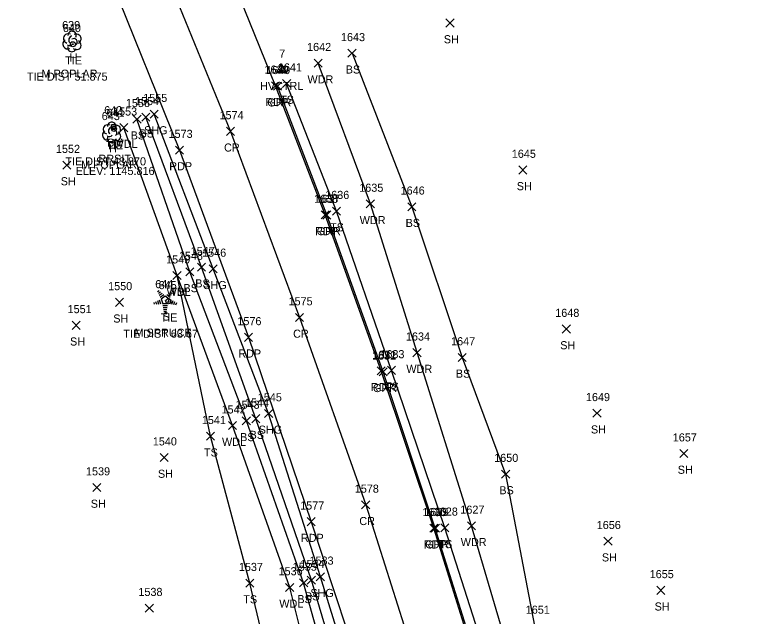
# Model space of a CAD drawing. Extents: x 1545627 to 1546562, y 571176 to 576667.
# Drawn here: x 1545906.1 to 1546091.5, y 572663.2 to 572811.9 of the extents above; entities that cross this region are included whole.
import ezdxf

# ---------------------------------------------------------------- set-up
doc = ezdxf.new("R2010")
doc.units = 0
for name, color, linetype in [('C_A', 7, 'Continuous'), ('C_C', 7, 'Continuous'), ('C_I', 7, 'Continuous'), ('CBP', 7, 'Continuous'), ('CPBM', 7, 'Continuous'), ('CPSM', 7, 'Continuous'), ('L_A', 7, 'Continuous'), ('L_C', 7, 'Continuous'), ('L_I', 7, 'Continuous'), ('L_TIC', 7, 'Continuous'), ('LAWA', 7, 'Continuous'), ('LELB', 7, 'Continuous'), ('LTC', 7, 'Continuous'), ('LTD', 7, 'Continuous'), ('P_A', 7, 'Continuous'), ('P_I', 7, 'Continuous'), ('P_TIC', 7, 'Continuous'), ('PET', 7, 'Continuous'), ('PRC', 7, 'Continuous'), ('PSU', 7, 'Continuous'), ('R_A', 7, 'Continuous'), ('R_I', 7, 'Continuous'), ('R_TIC', 7, 'Continuous'), ('RGR', 7, 'Continuous')]:
    doc.layers.add(name, color=color, linetype=linetype)

msp = doc.modelspace()

# ---------------------------------------------------------------- linework, layer by layer
at = {"layer": 'CBP'}
for centre, radius in [((1545920.38, 572804.67), 0.625), ((1545920.38, 572804.67), 0.0833), ((1545930.51, 572783.73), 0.625), ((1545930.51, 572783.73), 0.0833), ((1545943.94, 572741.15), 0.625), ((1545943.94, 572741.15), 0.0833)]:
    msp.add_circle(centre, radius, dxfattribs=at)
at = {"layer": 'CPBM'}
for p, q in [((1545929.99, 572783.86), (1545929.99, 572784.86)), ((1545929.99, 572784.86), (1545930.99, 572784.86)), ((1545930.5, 572784.36), (1545930.5, 572784.36)), ((1545930.5, 572784.36), (1545930.5, 572784.36)), ((1545930.99, 572784.86), (1545930.99, 572783.86)), ((1545930.99, 572783.86), (1545929.99, 572783.86))]:
    msp.add_line(p, q, dxfattribs=at)
at = {"layer": 'CPSM'}
for p, q in [((1545970.62, 572797.64), (1545971.87, 572799.81)), ((1545973.12, 572797.64), (1545971.87, 572799.81)), ((1545971.87, 572798.36), (1545971.87, 572799.81)), ((1545970.62, 572797.64), (1545971.87, 572798.36)), ((1545970.62, 572797.64), (1545973.12, 572797.64)), ((1545971.87, 572798.36), (1545971.87, 572798.36)), ((1545971.87, 572798.36), (1545973.12, 572797.64))]:
    msp.add_line(p, q, dxfattribs=at)
at = {"layer": 'L_TIC'}
for points in [[(1546012.47, 572808.9), (1546014.47, 572810.9)], [(1546014.47, 572808.9), (1546012.47, 572810.9)], [(1545988.29, 572801.43), (1545990.29, 572803.43)], [(1545990.29, 572801.43), (1545988.29, 572803.43)], [(1545979.93, 572798.99), (1545981.93, 572800.99)], [(1545981.93, 572798.99), (1545979.93, 572800.99)], [(1545972.14, 572793.95), (1545974.14, 572795.95)], [(1545974.14, 572793.95), (1545972.14, 572795.95)], [(1545935.18, 572785.14), (1545937.18, 572787.14)], [(1545937.18, 572785.14), (1545935.18, 572787.14)], [(1545937.38, 572785.62), (1545939.38, 572787.62)], [(1545939.38, 572785.62), (1545937.38, 572787.62)], [(1545931.96, 572783.05), (1545933.96, 572785.05)], [(1545933.96, 572783.05), (1545931.96, 572785.05)], [(1545917.86, 572773.81), (1545919.86, 572775.81)], [(1545919.86, 572773.81), (1545917.86, 572775.81)], [(1546030.48, 572772.6), (1546032.48, 572774.6)], [(1546032.48, 572772.6), (1546030.48, 572774.6)], [(1545992.81, 572764.21), (1545994.81, 572766.21)], [(1545994.81, 572764.21), (1545992.81, 572766.21)], [(1546003.07, 572763.52), (1546005.07, 572765.52)], [(1546005.07, 572763.52), (1546003.07, 572765.52)], [(1545984.45, 572762.44), (1545986.45, 572764.44)], [(1545986.45, 572762.44), (1545984.45, 572764.44)], [(1545948.22, 572747.41), (1545950.22, 572749.41)], [(1545950.22, 572747.41), (1545948.22, 572749.41)], [(1545951.14, 572748.58), (1545953.14, 572750.58)], [(1545953.14, 572748.58), (1545951.14, 572750.58)], [(1545945.07, 572746.5), (1545947.07, 572748.5)], [(1545947.07, 572746.5), (1545945.07, 572748.5)], [(1545945.07, 572746.5), (1545947.07, 572748.5)], [(1545947.07, 572746.5), (1545945.07, 572748.5)], [(1545930.84, 572739.9), (1545932.84, 572741.9)], [(1545932.84, 572739.9), (1545930.84, 572741.9)], [(1545920.18, 572734.22), (1545922.18, 572736.22)], [(1545922.18, 572734.22), (1545920.18, 572736.22)], [(1546041.21, 572733.3), (1546043.21, 572735.3)], [(1546043.21, 572733.3), (1546041.21, 572735.3)], [(1546004.34, 572727.46), (1546006.34, 572729.46)], [(1546006.34, 572727.46), (1546004.34, 572729.46)], [(1546015.49, 572726.28), (1546017.49, 572728.28)], [(1546017.49, 572726.28), (1546015.49, 572728.28)], [(1545998.02, 572723.09), (1546000.02, 572725.09)], [(1546000.02, 572723.09), (1545998.02, 572725.09)], [(1546048.79, 572712.49), (1546050.79, 572714.49)], [(1546050.79, 572712.49), (1546048.79, 572714.49)], [(1545962.2, 572710.6), (1545964.2, 572712.6)], [(1545964.2, 572710.6), (1545962.2, 572712.6)], [(1545964.55, 572711.15), (1545966.55, 572713.15)], [(1545966.55, 572711.15), (1545964.55, 572713.15)], [(1545958.77, 572709.44), (1545960.77, 572711.44)], [(1545960.77, 572709.44), (1545958.77, 572711.44)], [(1545953.32, 572706.82), (1545955.32, 572708.82)], [(1545955.32, 572706.82), (1545953.32, 572708.82)], [(1546070.23, 572702.53), (1546072.23, 572704.53)], [(1546072.23, 572702.53), (1546070.23, 572704.53)], [(1545941.87, 572701.54), (1545943.87, 572703.54)], [(1545943.87, 572701.54), (1545941.87, 572703.54)], [(1546026.22, 572697.47), (1546028.22, 572699.47)], [(1546028.22, 572697.47), (1546026.22, 572699.47)], [(1545925.29, 572694.14), (1545927.29, 572696.14)], [(1545927.29, 572694.14), (1545925.29, 572696.14)], [(1546011.21, 572684.19), (1546013.21, 572686.19)], [(1546013.21, 572684.19), (1546011.21, 572686.19)], [(1546017.77, 572684.67), (1546019.77, 572686.67)], [(1546019.77, 572684.67), (1546017.77, 572686.67)], [(1546051.5, 572680.88), (1546053.5, 572682.88)], [(1546053.5, 572680.88), (1546051.5, 572682.88)], [(1545978.25, 572671.26), (1545980.25, 572673.26)], [(1545980.25, 572671.26), (1545978.25, 572673.26)], [(1545963.04, 572670.52), (1545965.04, 572672.52)], [(1545965.04, 572670.52), (1545963.04, 572672.52)], [(1545972.9, 572669.46), (1545974.9, 572671.46)], [(1545974.9, 572669.46), (1545972.9, 572671.46)], [(1545976.34, 572670.58), (1545978.34, 572672.58)], [(1545978.34, 572670.58), (1545976.34, 572672.58)], [(1546064.53, 572668.75), (1546066.53, 572670.75)], [(1546066.53, 572668.75), (1546064.53, 572670.75)], [(1545938.23, 572664.35), (1545940.23, 572666.35)], [(1545940.23, 572664.35), (1545938.23, 572666.35)]]:
    msp.add_lwpolyline(points, dxfattribs=at)
at = {"layer": 'LAWA'}
for points in [[(1546132.7, 572194.89), (1546123.45, 572251.15), (1546111.94, 572304.9), (1546099.96, 572374.28), (1546086.11, 572421.03), (1546079.85, 572451.63), (1546071.91, 572496.17), (1546064.39, 572527.58), (1546058.59, 572548.65), (1546052.09, 572585.93), (1546038.43, 572619.67), (1546027.83, 572654.92), (1546018.77, 572685.67), (1546005.34, 572728.46), (1545993.81, 572765.21), (1545980.93, 572799.99)], [(1545984.07, 572612.3), (1545982.96, 572621.45), (1545978.9, 572650.64), (1545973.9, 572670.46), (1545959.77, 572710.44), (1545946.07, 572747.5), (1545932.96, 572784.05)]]:
    msp.add_lwpolyline(points, dxfattribs=at)
at = {"layer": 'LELB'}
for points in [[(1545989.29, 572802.43), (1546004.07, 572764.52), (1546016.49, 572727.28), (1546027.22, 572698.47), (1546034.36, 572660.96), (1546036.29, 572644.95)], [(1546125.53, 572192.44), (1546119.79, 572223.12), (1546112.54, 572267.48), (1546101.48, 572308.51), (1546092.3, 572354.82), (1546084.69, 572391.49), (1546079.39, 572418.94), (1546072.14, 572452.75), (1546063.27, 572495.37), (1546056.18, 572525.93), (1546052.45, 572548.06), (1546043.75, 572580.7), (1546033.1, 572617.26), (1546022.59, 572652.85), (1546012.21, 572685.19), (1545999.02, 572724.09), (1545985.45, 572763.44), (1545973.14, 572794.95)], [(1545956.48, 572590.69), (1545970.85, 572591.29), (1545971.25, 572594.64), (1545971.84, 572595.62), (1545977.17, 572605.73), (1545984.97, 572610.83), (1545994.97, 572606.43), (1545991.2, 572621.73), (1545977.34, 572671.58), (1545963.2, 572711.6), (1545949.22, 572748.41), (1545936.18, 572786.14)], [(1546057.72, 572296.67), (1546044.55, 572322.39), (1546039.4, 572343.5), (1546038.27, 572395.5), (1546040.06, 572418.12), (1546038.19, 572444), (1546032.75, 572474.34), (1546026.06, 572504.78), (1546024.23, 572513.12), (1546018.98, 572530.73), (1546011.95, 572554.6), (1546002.16, 572589.36), (1546002.67, 572591.46), (1546001.66, 572594.58), (1546000.81, 572597.18), (1545999.9, 572600.86), (1545993.99, 572622.54), (1545979.25, 572672.26), (1545965.55, 572712.15), (1545952.14, 572749.58), (1545938.38, 572786.62)], [(1545970.16, 572591.99), (1545966.12, 572604.73), (1545966.46, 572618.17), (1545969.88, 572647.01), (1545964.04, 572671.52), (1545954.32, 572707.82), (1545946.07, 572747.5)]]:
    msp.add_lwpolyline(points, dxfattribs=at)
at = {"layer": 'LTC'}
for p, q in [((1545941.28, 572743.6), (1545941.64, 572743.86)), ((1545941.49, 572743.13), (1545942.02, 572743.52)), ((1545944.31, 572743.49), (1545944.86, 572743.09)), ((1545944.68, 572743.84), (1545945.1, 572743.54)), ((1545941.68, 572741.53), (1545942.01, 572740.51)), ((1545941.7, 572742.67), (1545942.41, 572743.18)), ((1545941.91, 572742.2), (1545942.79, 572742.84)), ((1545942.14, 572741.75), (1545943.15, 572742.48)), ((1545942.14, 572741.75), (1545942.53, 572740.55)), ((1545943.15, 572742.48), (1545944.15, 572741.76)), ((1545943.57, 572742.79), (1545944.38, 572742.21)), ((1545944.15, 572741.76), (1545943.76, 572740.55)), ((1545943.94, 572743.14), (1545944.62, 572742.65)), ((1545944.58, 572741.49), (1545944.25, 572740.45)), ((1545940.32, 572740.88), (1545940.47, 572740.41)), ((1545940.77, 572741.1), (1545940.98, 572740.44)), ((1545941.23, 572741.31), (1545941.5, 572740.48)), ((1545943.76, 572740.55), (1545942.53, 572740.55)), ((1545943.72, 572740.05), (1545942.57, 572740.05)), ((1545943.63, 572739.55), (1545942.65, 572739.55)), ((1545945.03, 572741.24), (1545944.74, 572740.35)), ((1545945.47, 572740.99), (1545945.24, 572740.26)), ((1545945.92, 572740.74), (1545945.73, 572740.16)), ((1545943.55, 572739.05), (1545942.72, 572739.05)), ((1545943.47, 572738.55), (1545942.79, 572738.55))]:
    msp.add_line(p, q, dxfattribs=at)
at = {"layer": 'LTD'}
for p, q in [((1545920.11, 572805.39), (1545920.11, 572805.39)), ((1545920.11, 572805.39), (1545920.11, 572805.39)), ((1545929.89, 572782.92), (1545929.89, 572782.92)), ((1545929.89, 572782.92), (1545929.89, 572782.92))]:
    msp.add_line(p, q, dxfattribs=at)
for centre in [(1545920.16, 572806.82), (1545929.93, 572784.35)]:
    msp.add_arc(centre, 1.05, 335.5272, 180.9563, dxfattribs=at)
for centre, major_axis, ratio, start_param, end_param in [((1545919.32, 572806.05), (1.21, -0.51), 0.895232, 1.570796, 4.712389), ((1545919.9, 572805.84), (-0.208, -0.792), 0.645439, 3.141593, 6.283185), ((1545921.15, 572805.97), (-1.14, -0.48), 0.949671, 1.570796, 4.712389), ((1545919.03, 572804.68), (0.58, -1.04), 0.959034, 3.141593, 6.283185), ((1545919.65, 572804.64), (-0.625, -0.083), 0.423636, 0, 3.141593), ((1545920.61, 572805.22), (-0.5, 0.667), 0.989748, 3.141593, 6.283185), ((1545921.11, 572804.55), (-1.09, 0.79), 0.841452, 1.570796, 4.712389), ((1545920.11, 572803.89), (0.26, 1.06), 0.942809, 1.570796, 4.712389), ((1545929.1, 572783.58), (1.21, -0.51), 0.895232, 1.570796, 4.712389), ((1545929.68, 572783.37), (-0.208, -0.792), 0.645439, 3.141593, 6.283185), ((1545930.93, 572783.5), (-1.14, -0.48), 0.949671, 1.570796, 4.712389), ((1545928.8, 572782.21), (0.58, -1.04), 0.959034, 3.141593, 6.283185), ((1545929.43, 572782.17), (-0.625, -0.083), 0.423636, 0, 3.141593), ((1545930.39, 572782.75), (-0.5, 0.667), 0.989748, 3.141593, 6.283185), ((1545930.89, 572782.08), (-1.09, 0.79), 0.841452, 1.570796, 4.712389), ((1545929.89, 572781.42), (0.26, 1.06), 0.942809, 1.570796, 4.712389)]:
    msp.add_ellipse(centre, major_axis=major_axis, ratio=ratio, start_param=start_param, end_param=end_param, dxfattribs=at)
at = {"layer": 'P_TIC'}
for points in [[(1545969.4, 572793.41), (1545971.4, 572795.41)], [(1545971.4, 572793.41), (1545969.4, 572795.41)], [(1545939.4, 572786.41), (1545941.4, 572788.41)], [(1545941.4, 572786.41), (1545939.4, 572788.41)], [(1545958.26, 572782.14), (1545960.26, 572784.14)], [(1545960.26, 572782.14), (1545958.26, 572784.14)], [(1545945.67, 572777.52), (1545947.67, 572779.52)], [(1545947.67, 572777.52), (1545945.67, 572779.52)], [(1545981.66, 572761.49), (1545983.66, 572763.49)], [(1545983.66, 572761.49), (1545981.66, 572763.49)], [(1545954.02, 572748.17), (1545956.02, 572750.17)], [(1545956.02, 572748.17), (1545954.02, 572750.17)], [(1545975.31, 572736.15), (1545977.31, 572738.15)], [(1545977.31, 572736.15), (1545975.31, 572738.15)], [(1545962.72, 572731.25), (1545964.72, 572733.25)], [(1545964.72, 572731.25), (1545962.72, 572733.25)], [(1545995.46, 572722.96), (1545997.46, 572724.96)], [(1545997.46, 572722.96), (1545995.46, 572724.96)], [(1545967.7, 572712.44), (1545969.7, 572714.44)], [(1545969.7, 572712.44), (1545967.7, 572714.44)], [(1545991.66, 572689.86), (1545993.66, 572691.86)], [(1545993.66, 572689.86), (1545991.66, 572691.86)], [(1545978.17, 572685.7), (1545980.17, 572687.7)], [(1545980.17, 572685.7), (1545978.17, 572687.7)], [(1546008.49, 572684.07), (1546010.49, 572686.07)], [(1546010.49, 572684.07), (1546008.49, 572686.07)], [(1545980.47, 572672.09), (1545982.47, 572674.09)], [(1545982.47, 572672.09), (1545980.47, 572674.09)]]:
    msp.add_lwpolyline(points, dxfattribs=at)
at = {"layer": 'PET'}
for points in [[(1546060.5, 572495.35), (1546051.12, 572536.86), (1546040.85, 572577.55), (1546029.96, 572616.83), (1546019.8, 572652.17), (1546009.49, 572685.07), (1545996.46, 572723.96), (1545982.66, 572762.49), (1545970.4, 572794.41), (1545953.97, 572834.9)], [(1545929.79, 572820.4), (1545946.67, 572778.52), (1545963.72, 572732.25), (1545979.17, 572686.7), (1545993.79, 572642.56), (1546006.51, 572598.13), (1546019.19, 572549.75), (1546028.2, 572511.71)]]:
    msp.add_lwpolyline(points, dxfattribs=at)
at = {"layer": 'PRC'}
msp.add_lwpolyline([(1545789.97, 573149.91), (1545812.75, 573103.84), (1545835.71, 573057.35), (1545858.01, 573011.3), (1545880.3, 572964.26), (1545901.33, 572918.7), (1545921.74, 572873.14), (1545941.5, 572826.68), (1545959.26, 572783.14), (1545976.31, 572737.15), (1545992.66, 572690.86), (1546006.78, 572646.35), (1546020.38, 572601.27), (1546032.77, 572553.22), (1546041.68, 572514.93), (1546051.79, 572470.3), (1546061.81, 572422.58), (1546071.32, 572378), (1546081.35, 572330.37), (1546091.01, 572283.41), (1546102.06, 572230), (1546107.88, 572201.7), (1546113.19, 572174.92)], dxfattribs=at)
at = {"layer": 'PSU'}
msp.add_lwpolyline([(1546039.81, 572443.48), (1546034.13, 572474.72), (1546027.46, 572506.01), (1546025.72, 572513.44), (1546021.61, 572531.25), (1546014.99, 572555.06), (1546006.32, 572589.9), (1545996.64, 572624.03), (1545981.47, 572673.09), (1545968.7, 572713.44), (1545955.02, 572749.17), (1545940.4, 572787.41)], dxfattribs=at)
at = {"layer": 'R_TIC'}
for points in [[(1545969.88, 572793.29), (1545971.88, 572795.29)], [(1545971.88, 572793.29), (1545969.88, 572795.29)], [(1545982.08, 572761.48), (1545984.08, 572763.48)], [(1545984.08, 572761.48), (1545982.08, 572763.48)], [(1545995.97, 572722.72), (1545997.97, 572724.72)], [(1545997.97, 572722.72), (1545995.97, 572724.72)], [(1546008.86, 572684.1), (1546010.86, 572686.1)], [(1546010.86, 572684.1), (1546008.86, 572686.1)]]:
    msp.add_lwpolyline(points, dxfattribs=at)
at = {"layer": 'RGR'}
msp.add_lwpolyline([(1546122.9, 572190.91), (1546117.32, 572223.34), (1546108.74, 572265.6), (1546099.88, 572308.9), (1546090.29, 572354.45), (1546082.74, 572391.05), (1546076.81, 572419.12), (1546069.97, 572452.17), (1546060.89, 572495.21), (1546054.25, 572525.61), (1546048.91, 572547.32), (1546040.71, 572580.21), (1546030.58, 572616.09), (1546020.22, 572652.04), (1546009.86, 572685.1), (1545996.97, 572723.72), (1545983.08, 572762.48), (1545970.88, 572794.29)], dxfattribs=at)

# ---------------------------------------------------------------- texts
at = {"layer": 'C_A'}
for s, p in [('TIE', (1545918.46, 572799.67)), ('HVCTRL', (1545966.57, 572793.36)), ('TIE', (1545928.59, 572778.73)), ('BM', (1545928.81, 572779.36)), ('TIE', (1545942.02, 572736.15))]:
    msp.add_text(s, height=2, dxfattribs=at).set_placement(p)
at = {"layer": 'C_C'}
for s, p in [('TIE DIST 51.875', (1545909.02, 572795.67)), ('TIE DIST 43.870', (1545918.5, 572774.73)), ('RRSIT', (1545926.68, 572775.36)), ('ELEV: 1145.816', (1545921.05, 572772.36)), ('TIE DIST 63.67', (1545932.82, 572732.15))]:
    msp.add_text(s, height=2, dxfattribs=at).set_placement(p)
at = {"layer": 'C_I'}
for s, p in [('640', (1545917.88, 572807.67)), ('7', (1545971.31, 572801.36)), ('642', (1545928.09, 572787.36)), ('641', (1545928.67, 572786.73)), ('645', (1545941.53, 572744.15))]:
    msp.add_text(s, height=2, dxfattribs=at).set_placement(p)
at = {"layer": 'L_A'}
for s, p in [('SH', (1546011.95, 572804.9)), ('H', (1545919.54, 572800.39)), ('BS', (1545987.73, 572797.43)), ('WDR', (1545978.29, 572794.99)), ('TS', (1545971.55, 572789.95)), ('BS', (1545934.62, 572781.14)), ('BS', (1545936.82, 572781.62)), ('WDL', (1545930.38, 572779.05)), ('H', (1545929.32, 572777.92)), ('SH', (1545917.35, 572769.81)), ('SH', (1546029.97, 572768.6)), ('WDR', (1545991.18, 572760.21)), ('TS', (1545983.86, 572758.44)), ('BS', (1546002.52, 572759.52)), ('BS', (1545947.66, 572743.41)), ('BS', (1545950.58, 572744.58)), ('WDL', (1545943.49, 572742.5)), ('TS', (1545944.48, 572742.5)), ('SH', (1545930.33, 572735.9)), ('S', (1545942.48, 572736.39)), ('SH', (1545919.66, 572730.22)), ('SH', (1546040.7, 572729.3)), ('WDR', (1546002.7, 572723.46)), ('BS', (1546014.93, 572722.28)), ('TS', (1545997.43, 572719.09)), ('SH', (1546048.28, 572708.49)), ('BS', (1545961.64, 572706.6)), ('BS', (1545963.99, 572707.15)), ('WDL', (1545957.18, 572705.44)), ('TS', (1545952.73, 572702.82)), ('SH', (1545941.36, 572697.54)), ('SH', (1546069.72, 572698.53)), ('BS', (1546025.66, 572693.47)), ('SH', (1545924.77, 572690.14)), ('TS', (1546010.62, 572680.19)), ('WDR', (1546016.13, 572680.67)), ('SH', (1546050.99, 572676.88)), ('BS', (1545977.69, 572667.26)), ('TS', (1545962.44, 572666.52)), ('WDL', (1545971.32, 572665.46)), ('BS', (1545975.78, 572666.58)), ('SH', (1546064.01, 572664.75))]:
    msp.add_text(s, height=2, dxfattribs=at).set_placement(p)
at = {"layer": 'L_C'}
for s, p in [('M POPLAR', (1545912.61, 572796.39)), ('M POPLAR', (1545922.38, 572773.92)), ('M SPRUCE', (1545935.59, 572732.39))]:
    msp.add_text(s, height=2, dxfattribs=at).set_placement(p)
at = {"layer": 'L_I'}
for s, p in [('639', (1545917.69, 572808.39)), ('1643', (1545986.55, 572805.43)), ('1642', (1545978.19, 572802.99)), ('1641', (1545970.96, 572797.95)), ('1554', (1545935.69, 572789.62)), ('1556', (1545933.43, 572789.14)), ('643', (1545927.48, 572785.92)), ('1553', (1545930.27, 572787.05)), ('1552', (1545916.17, 572777.81)), ('1645', (1546028.74, 572776.6)), ('1635', (1545991.07, 572768.21)), ('1646', (1546001.28, 572767.52)), ('1636', (1545982.66, 572766.44)), ('1547', (1545949.45, 572752.58)), ('1548', (1545946.53, 572751.41)), ('1549', (1545943.37, 572750.5)), ('1549', (1545943.37, 572750.5)), ('1550', (1545929.06, 572743.9)), ('644', (1545940.68, 572744.39)), ('1551', (1545919.05, 572738.22)), ('1648', (1546039.47, 572737.3)), ('1634', (1546002.6, 572731.46)), ('1647', (1546013.75, 572730.28)), ('1633', (1545996.28, 572727.09)), ('1649', (1546047.04, 572716.49)), ('1542', (1545957.07, 572713.44)), ('1543', (1545960.51, 572714.6)), ('1544', (1545962.86, 572715.15)), ('1541', (1545952.19, 572710.82)), ('1657', (1546068.49, 572706.53)), ('1540', (1545940.09, 572705.54)), ('1650', (1546024.39, 572701.47)), ('1539', (1545923.59, 572698.14)), ('1628', (1546009.47, 572688.19)), ('1627', (1546016.03, 572688.67)), ('1656', (1546049.71, 572684.88)), ('1537', (1545961.34, 572674.52)), ('1535', (1545974.64, 572674.58)), ('1534', (1545976.55, 572675.26)), ('1536', (1545971.15, 572673.46)), ('1655', (1546062.79, 572672.75)), ('1538', (1545936.53, 572668.35)), ('1651', (1546032.18, 572663.96))]:
    msp.add_text(s, height=2, dxfattribs=at).set_placement(p)
at = {"layer": 'LTC'}
msp.add_text('.', height=1.04, rotation=270, dxfattribs=at).set_placement((1545943.03, 572741.5))
at = {"layer": 'P_A'}
for s, p in [('RDP', (1545967.89, 572789.41)), ('SHG', (1545937.94, 572782.41)), ('CR', (1545957.69, 572778.14)), ('RDP', (1545944.16, 572773.52)), ('RDP', (1545980.15, 572757.49)), ('SHG', (1545952.55, 572744.17)), ('CR', (1545974.74, 572732.15)), ('RDP', (1545961.2, 572727.25)), ('RDP', (1545993.94, 572718.96)), ('SHG', (1545966.24, 572708.44)), ('CR', (1545991.09, 572685.86)), ('RDP', (1545976.66, 572681.7)), ('RDP', (1546006.98, 572680.07)), ('SHG', (1545979, 572668.09))]:
    msp.add_text(s, height=2, dxfattribs=at).set_placement(p)
at = {"layer": 'P_I'}
for s, p in [('1639', (1545967.66, 572797.41)), ('1555', (1545937.71, 572790.41)), ('1574', (1545956.56, 572786.14)), ('1573', (1545943.98, 572781.52)), ('1638', (1545979.92, 572765.49)), ('1546', (1545952.27, 572752.17)), ('1575', (1545973.61, 572740.15)), ('1576', (1545960.97, 572735.25)), ('1631', (1545994.28, 572726.96)), ('1545', (1545966.01, 572716.44)), ('1578', (1545989.96, 572693.86)), ('1577', (1545976.48, 572689.7)), ('1630', (1546006.66, 572688.07)), ('1533', (1545978.78, 572676.09))]:
    msp.add_text(s, height=2, dxfattribs=at).set_placement(p)
at = {"layer": 'R_A'}
for p in [(1545968.37, 572789.29), (1545980.57, 572757.48), (1545994.46, 572718.72), (1546007.35, 572680.1)]:
    msp.add_text('GRR', height=2, dxfattribs=at).set_placement(p)
at = {"layer": 'R_I'}
for s, p in [('1640', (1545968.05, 572797.29)), ('1637', (1545980.34, 572765.48)), ('1632', (1545994.23, 572726.72)), ('1629', (1546007.11, 572688.1))]:
    msp.add_text(s, height=2, dxfattribs=at).set_placement(p)

doc.saveas('drawing.dxf')
